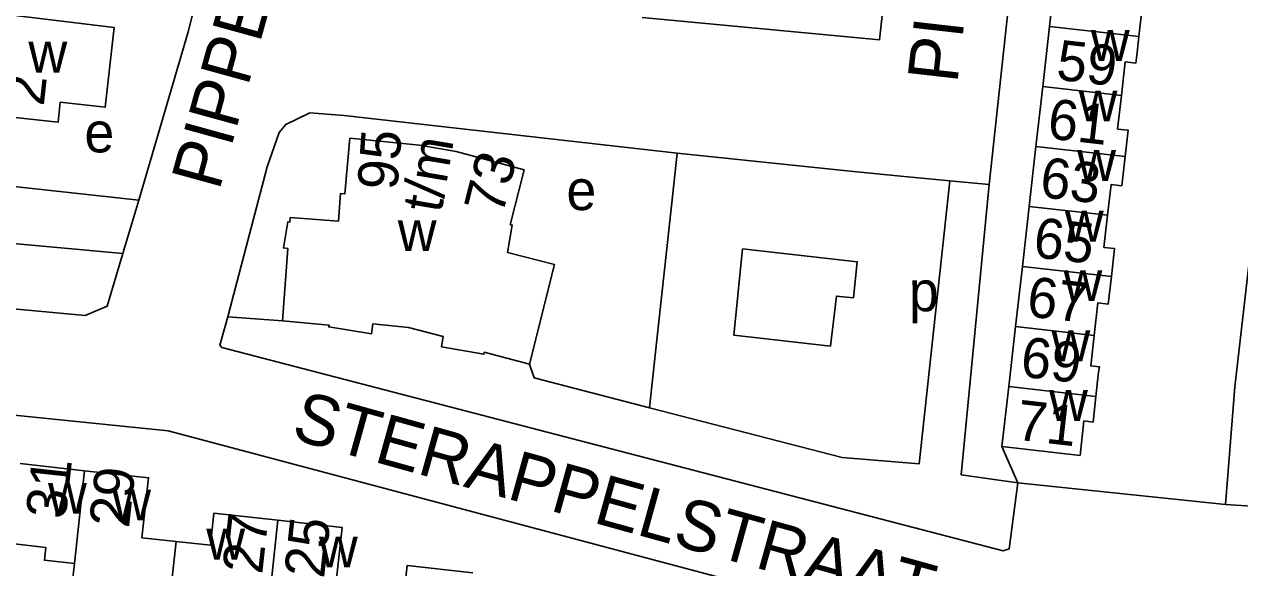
# Model space of a CAD drawing. Extents: x 161936 to 163647, y 386450 to 388633.
# Drawn here: x 162347.8 to 162468.8, y 387793.6 to 387847.8 of the extents above; entities that cross this region are included whole.
import ezdxf

# ---------------------------------------------------------------- set-up
doc = ezdxf.new("R2010")
doc.units = 0
for name, color, linetype in [('BLT_Basislijn', 7, 'Continuous'), ('BLT_Bebouwing', 7, 'Continuous'), ('BLT_Centroide', 7, 'Continuous'), ('BLT_Huisnummer', 7, 'Continuous'), ('BLT_Huisnummer_ tussenligend', 7, 'Continuous'), ('BLT_Huisnummer_reeks', 7, 'Continuous'), ('BLT_Onderverdeling_panden', 7, 'Continuous'), ('BLT_Straatnaam', 7, 'Continuous'), ('BLT_Vlakafsluiter', 7, 'Continuous')]:
    doc.layers.add(name, color=color, linetype=linetype)

msp = doc.modelspace()

# ---------------------------------------------------------------- linework, layer by layer
at = {"layer": 'BLT_Basislijn'}
for p, q in [((162443.87, 387831.81), (162447.54, 387865.89)), ((162412.22, 387829.68), (162412.79, 387834.92)), ((162430.03, 387833.14), (162435.08, 387832.62)), ((162439.95, 387832.17), (162435.08, 387832.62)), ((162443.87, 387831.81), (162439.95, 387832.17)), ((162357.56, 387824.92), (162359.18, 387830.23)), ((162410.76, 387816.32), (162412.22, 387829.68)), ((162368.03, 387818.61), (162373.47, 387818.23)), ((162410.02, 387809.56), (162410.76, 387816.32)), ((162446.72, 387802.08), (162467.39, 387799.91)), ((162467.39, 387799.91), (162473.55, 387799.55))]:
    msp.add_line(p, q, dxfattribs=at)
for points in [[(162432.52, 387892.01), (162437.9, 387891.45), (162432.93, 387846.2), (162409.3, 387848.45)], [(162474.95, 387869.17), (162468.35, 387811.65), (162467.39, 387799.91)], [(162359.18, 387830.23), (162307.26, 387835.93), (162308.67, 387851.24), (162310.34, 387865.26)], [(162366.61, 387856.95), (162364.09, 387847.01), (162359.18, 387830.23)], [(162412.79, 387834.92), (162379.61, 387838.68), (162376.19, 387838.95), (162373.8, 387837.77), (162373.16, 387836.98), (162371.95, 387833.56), (162368.28, 387819.51), (162368.03, 387818.61)], [(162412.79, 387834.92), (162430.03, 387833.14)], [(162429.22, 387804.6), (162436.88, 387803.96), (162439.95, 387832.17)], [(162446.72, 387802.08), (162441.07, 387802.88), (162443.87, 387831.81)], [(162357.56, 387824.92), (162307.37, 387829.52), (162306.53, 387823.36)], [(162306.53, 387823.36), (162309.83, 387822.82), (162353.81, 387818.74), (162356.03, 387819.69), (162357.56, 387824.92)], [(162368.03, 387818.61), (162367.24, 387815.81), (162367.43, 387815.55), (162445.27, 387795.29), (162445.85, 387795.49), (162446.72, 387802.08)], [(162398.08, 387813.9), (162398.54, 387812.53), (162410.02, 387809.56)], [(162303.81, 387812.76), (162305.9, 387812.89), (162310.22, 387812.55), (162362.08, 387807.27), (162442.89, 387785.78), (162486.12, 387780.93), (162488.41, 387779.48), (162488.92, 387778.18), (162485.87, 387747.39)], [(162410.02, 387809.56), (162429.22, 387804.6)]]:
    msp.add_lwpolyline(points, dxfattribs=at)
msp.add_lwpolyline([(162419.29, 387825.4), (162430.72, 387824.11), (162430.35, 387820.52), (162428.65, 387820.68), (162428.06, 387815.7), (162418.42, 387816.8)], close=True, dxfattribs=at)
at = {"layer": 'BLT_Bebouwing'}
for p, q in [((162450.56, 387853.53), (162449.88, 387847.55)), ((162449.88, 387847.55), (162449.21, 387841.57)), ((162449.21, 387841.57), (162448.53, 387835.59)), ((162448.53, 387835.59), (162447.85, 387829.61)), ((162447.85, 387829.61), (162447.17, 387823.64)), ((162447.17, 387823.64), (162446.5, 387817.66)), ((162446.5, 387817.66), (162445.82, 387811.68)), ((162347.35, 387804), (162353.77, 387803.29))]:
    msp.add_line(p, q, dxfattribs=at)
for points in [[(162458.78, 387846.54), (162459.07, 387849.14), (162457.98, 387849.26), (162458.36, 387852.65)], [(162345.45, 387848.8), (162356.7, 387847.44), (162355.82, 387839.49), (162351.34, 387839.99)], [(162457.04, 387840.68), (162457.42, 387844.02), (162458.48, 387843.9), (162458.6, 387844.95), (162458.78, 387846.54)], [(162457.4, 387834.59), (162457.7, 387837.22), (162456.66, 387837.33), (162457.04, 387840.68)], [(162351.34, 387839.99), (162351.12, 387838), (162344.34, 387838.75)], [(162380.17, 387836.43), (162379.7, 387830.86), (162379.27, 387830.89), (162379.06, 387828.15), (162374.25, 387828.51), (162374.22, 387828.06), (162374.02, 387828.09), (162373.57, 387825.48), (162374.02, 387825.41), (162373.47, 387818.23)], [(162397.54, 387833.26), (162390.79, 387835.08), (162387.11, 387835.73), (162380.17, 387836.43)], [(162455.66, 387828.73), (162456.01, 387831.79), (162457.07, 387831.67), (162457.4, 387834.59)], [(162398.08, 387813.9), (162400.57, 387823.84), (162395.89, 387825.02), (162396.36, 387827.76), (162396.16, 387827.79), (162397.54, 387833.26)], [(162456.04, 387822.63), (162456.36, 387825.42), (162455.3, 387825.54), (162455.66, 387828.73)], [(162456.04, 387822.63), (162455.73, 387819.89), (162454.7, 387820), (162454.33, 387816.77)], [(162373.47, 387818.23), (162378.12, 387817.8), (162378.08, 387817.61), (162382.33, 387816.92), (162382.49, 387817.93), (162386.02, 387817.57), (162389.48, 387816.65), (162389.3, 387815.63), (162393.54, 387814.89), (162393.57, 387815.09), (162398.08, 387813.9)], [(162454.33, 387816.77), (162453.99, 387813.73), (162454.84, 387813.64), (162454.77, 387813.1), (162454.5, 387810.69)], [(162445.82, 387811.68), (162445.14, 387805.7)], [(162445.14, 387805.7), (162452.92, 387804.81), (162453.3, 387808.24), (162454.21, 387808.13), (162454.5, 387810.69)], [(162353.77, 387803.29), (162360.14, 387802.59), (162359.48, 387796.61), (162362.89, 387796.24)], [(162362.89, 387796.24), (162366.29, 387795.86), (162366.64, 387799.05), (162373.02, 387798.35)], [(162373.02, 387798.35), (162379.42, 387797.64), (162378.76, 387791.64), (162382.14, 387791.27)], [(162352.75, 387794.03), (162349.76, 387794.36), (162349.9, 387795.65), (162346.47, 387796.03)], [(162361.89, 387787.14), (162361.69, 387785.37), (162358.19, 387785.76), (162358.81, 387791.33), (162352.53, 387792.02), (162352.75, 387794.03)], [(162382.14, 387791.27), (162385.56, 387790.89), (162385.88, 387793.84), (162392.44, 387793.12)]]:
    msp.add_lwpolyline(points, dxfattribs=at)
at = {"layer": 'BLT_Onderverdeling_panden'}
for p, q in [((162449.88, 387847.55), (162458.78, 387846.54)), ((162449.21, 387841.57), (162457.04, 387840.68)), ((162448.53, 387835.59), (162457.4, 387834.59)), ((162447.85, 387829.61), (162455.66, 387828.73)), ((162447.17, 387823.64), (162456.04, 387822.63)), ((162446.5, 387817.66), (162454.33, 387816.77)), ((162445.82, 387811.68), (162454.5, 387810.69)), ((162353.77, 387803.29), (162352.75, 387794.03)), ((162372.1, 387789.95), (162373.02, 387798.35)), ((162362.89, 387796.24), (162361.89, 387787.14))]:
    msp.add_line(p, q, dxfattribs=at)
at = {"layer": 'BLT_Vlakafsluiter'}
msp.add_line((162445.14, 387805.7), (162446.72, 387802.08), dxfattribs=at)

# ---------------------------------------------------------------- texts
at = {"layer": 'BLT_Centroide'}
for s, p in [('w', (162454, 387844.12)), ('w', (162348.17, 387842.95)), ('w', (162452.78, 387838.09)), ('e', (162353.75, 387835)), ('w', (162452.63, 387832.16)), ('e', (162401.76, 387829.25)), ('w', (162451.41, 387826.12)), ('w', (162384.96, 387825.16)), ('w', (162451.27, 387820.19)), ('p', (162435.87, 387819.17)), ('w', (162450.07, 387814.19)), ('w', (162449.83, 387808.25)), ('w', (162350.12, 387799)), ('w', (162356.52, 387798.34)), ('w', (162365.89, 387794.44)), ('w', (162377.11, 387793.66))]:
    msp.add_text(s, height=4, dxfattribs=at).set_placement(p)
at = {"layer": 'BLT_Huisnummer'}
for s, rotation, p in [('59', 353.5314, (162450.45, 387842.26)), ('2', 83.6893, (162349.69, 387839.54)), ('63', 353.5309, (162448.81, 387830.57)), ('67', 353.5314, (162447.51, 387818.68)), ('71', 353.5345, (162446.45, 387806.39)), ('29', 83.7146, (162358.18, 387797.5)), ('25', 83.7268, (162377.61, 387792.49))]:
    msp.add_text(s, height=4, rotation=rotation, dxfattribs=at).set_placement(p)
at = {"layer": 'BLT_Huisnummer_ tussenligend'}
for s, rotation, p in [('61', 353.5309, (162449.57, 387836.41)), ('65', 353.5314, (162448.16, 387824.57)), ('69', 353.5314, (162446.88, 387812.68)), ('31', 83.7146, (162351.86, 387798.38)), ('27', 83.7268, (162371.45, 387792.9))]:
    msp.add_text(s, height=4, rotation=rotation, dxfattribs=at).set_placement(p)
at = {"layer": 'BLT_Huisnummer_reeks'}
for s, rotation, p in [('95', 85.6629, (162384.91, 387831.17)), ('t/m', 80.3107, (162389.3, 387828.88)), ('73', 75.9041, (162395.39, 387828.66))]:
    msp.add_text(s, height=4, rotation=rotation, dxfattribs=at).set_placement(p)
at = {"layer": 'BLT_Straatnaam'}
for s, rotation, p in [('PIPPELINGSTRAAT', 83.5231, (162440.69, 387841.8)), ('PIPPELINGSTRAAT', 74.5987, (162367.17, 387831.1)), ('STERAPPELSTRAAT', 344.4852, (162374.22, 387806.5))]:
    msp.add_text(s, height=5, rotation=rotation, dxfattribs=at).set_placement(p)

doc.saveas('drawing.dxf')
